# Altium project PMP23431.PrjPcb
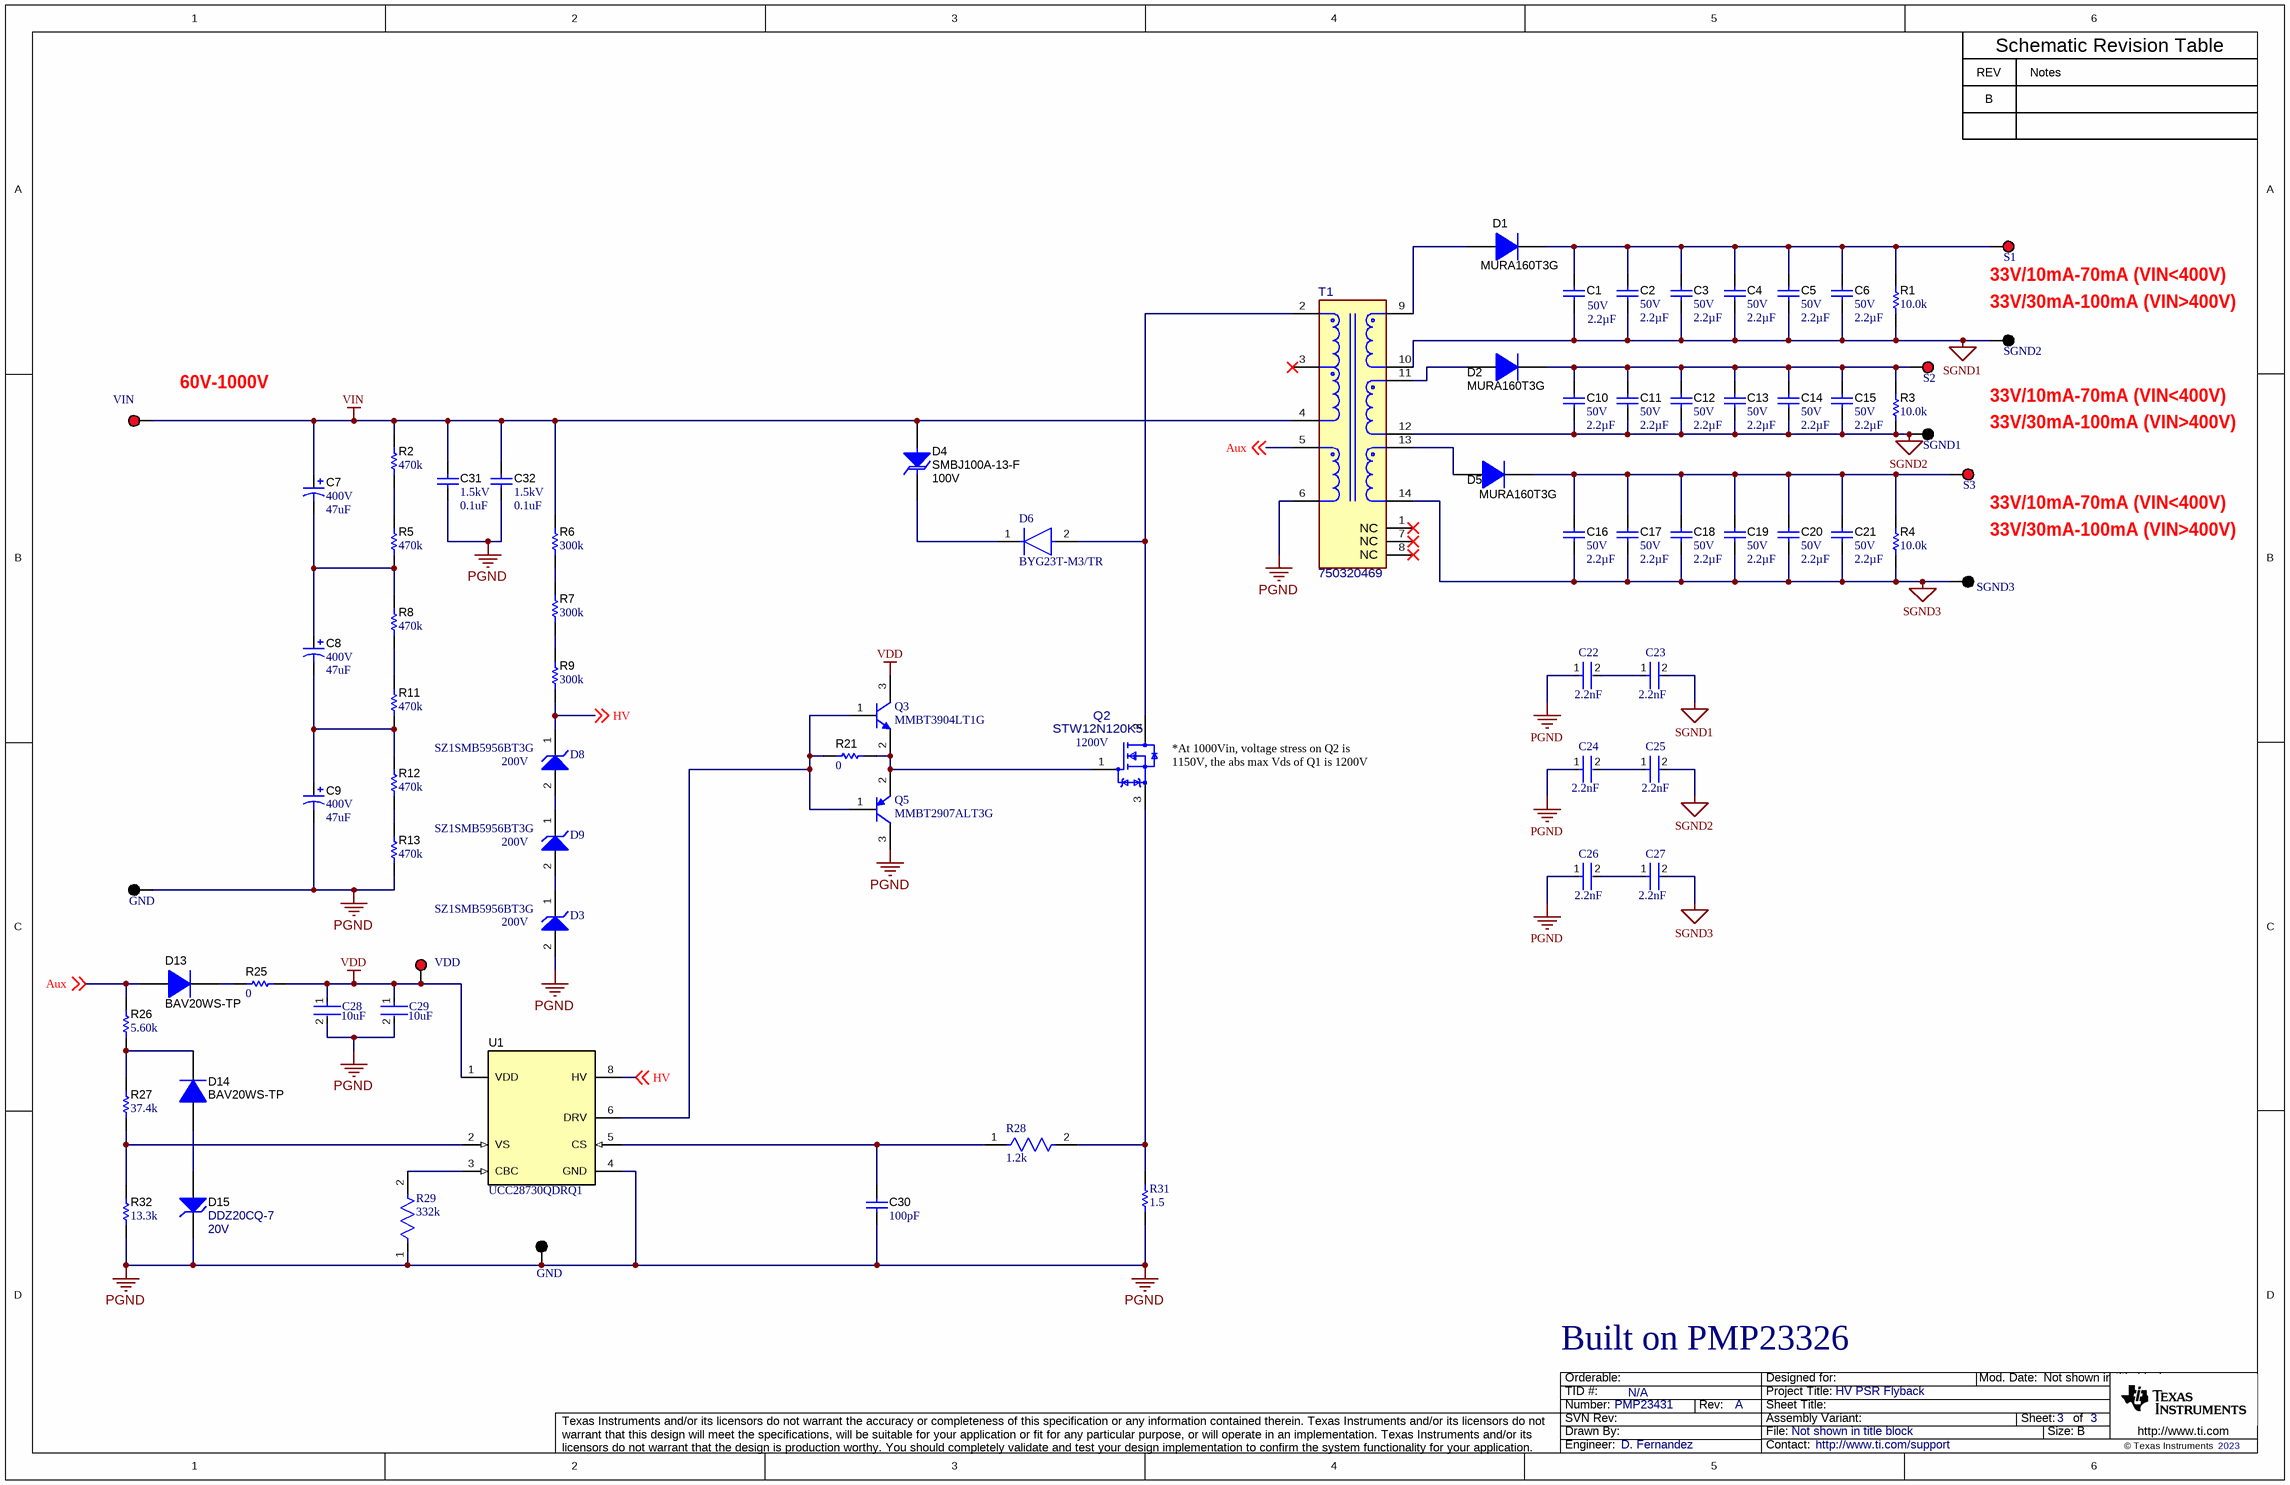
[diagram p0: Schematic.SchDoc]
CopyrightYear: 2023; PCB_Rev: A; PRJ_Engineer: D. Fernandez; PRJ_Number: PMP23431; PRJ_Title: HV PSR Flyback; SCH_Rev: A; TechSupport: http://www.ti.com/support; TID: N/A
1 sheet, 78 parts. Net scope: global (net labels, ports and power ports of the same name join across sheets).
Board file: Pcb.PcbDoc

## Sheet Schematic.SchDoc
size 431 x 279 mm; Date: Not shown in title block; ApprovedBy: Not shown in title block; CheckedBy: Not shown in title block; Author: Not shown in title block; CompanyName: Not shown in title block; Engineer: Not shown in title block; Organization: Not shown in title block; Address1: Not shown in title block; Address2: Not shown in title block; Address3: Not shown in title block; Address4: Not shown in title block; DocumentNumber: 3; Revision: Use project parameter SCH_Rev; SheetNumber: 3; SheetTotal: 3; PageSetup: Record=PageOptions¦CenterHorizontal=True¦CenterVertical=True¦PrintScale=1.00¦XCorrection=1.00¦YCorrection=1.00¦PrintKind=0¦BorderSize=5000000¦LeftOffset=0¦BottomOffset=0¦Orientation=2¦PaperLength=1000¦PaperWidth=1000¦Scale=100¦PaperSource=15¦PrintQuality=600¦MediaType=1¦DitherType=10¦PaperKind=Letter¦PrintScaleMode=1

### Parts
(Parts that share a designator on the sheet are numbered #1, #2 ... from top to bottom, then left to right.)
C1  VDC_V: 50V  ValueDisplayed: 2.2µF  [1206_180]  (hidden comment: UMJ316AB7225KLHT)
C2  VDC_V: 50V  ValueDisplayed: 2.2µF  [1206_180]  (hidden comment: UMJ316AB7225KLHT)
C3  VDC_V: 50V  ValueDisplayed: 2.2µF  [1206_180]  (hidden comment: UMJ316AB7225KLHT)
C4  VDC_V: 50V  ValueDisplayed: 2.2µF  [1206_180]  (hidden comment: UMJ316AB7225KLHT)
C5  VDC_V: 50V  ValueDisplayed: 2.2µF  [1206_180]  (hidden comment: UMJ316AB7225KLHT)
C6  VDC_V: 50V  ValueDisplayed: 2.2µF  [1206_180]  (hidden comment: UMJ316AB7225KLHT)
C7  VDC_V: 400V  ValueDisplayed: 47uF  [EE_1800x2000]  (hidden comment: EEU-EE2G470S)
C8  VDC_V: 400V  ValueDisplayed: 47uF  [EE_1800x2000]  (hidden comment: EEU-EE2G470S)
C9  VDC_V: 400V  ValueDisplayed: 47uF  [EE_1800x2000]  (hidden comment: EEU-EE2G470S)
C10  VDC_V: 50V  ValueDisplayed: 2.2µF  [1206_180]  (hidden comment: UMJ316AB7225KLHT)
C11  VDC_V: 50V  ValueDisplayed: 2.2µF  [1206_180]  (hidden comment: UMJ316AB7225KLHT)
C12  VDC_V: 50V  ValueDisplayed: 2.2µF  [1206_180]  (hidden comment: UMJ316AB7225KLHT)
C13  VDC_V: 50V  ValueDisplayed: 2.2µF  [1206_180]  (hidden comment: UMJ316AB7225KLHT)
C14  VDC_V: 50V  ValueDisplayed: 2.2µF  [1206_180]  (hidden comment: UMJ316AB7225KLHT)
C15  VDC_V: 50V  ValueDisplayed: 2.2µF  [1206_180]  (hidden comment: UMJ316AB7225KLHT)
C16  VDC_V: 50V  ValueDisplayed: 2.2µF  [1206_180]  (hidden comment: UMJ316AB7225KLHT)
C17  VDC_V: 50V  ValueDisplayed: 2.2µF  [1206_180]  (hidden comment: UMJ316AB7225KLHT)
C18  VDC_V: 50V  ValueDisplayed: 2.2µF  [1206_180]  (hidden comment: UMJ316AB7225KLHT)
C19  VDC_V: 50V  ValueDisplayed: 2.2µF  [1206_180]  (hidden comment: UMJ316AB7225KLHT)
C20  VDC_V: 50V  ValueDisplayed: 2.2µF  [1206_180]  (hidden comment: UMJ316AB7225KLHT)
C21  VDC_V: 50V  ValueDisplayed: 2.2µF  [1206_180]  (hidden comment: UMJ316AB7225KLHT)
C22  Capacitance: 2.2nF  [FP-C4532-130-MFG]  (hidden comment: C4532X7R3D222K130KA)
C23  Capacitance: 2.2nF  [FP-C4532-130-MFG]  (hidden comment: C4532X7R3D222K130KA)
C24  Capacitance: 2.2nF  [FP-C4532-130-MFG]  (hidden comment: C4532X7R3D222K130KA)
C25  Capacitance: 2.2nF  [FP-C4532-130-MFG]  (hidden comment: C4532X7R3D222K130KA)
C26  Capacitance: 2.2nF  [FP-C4532-130-MFG]  (hidden comment: C4532X7R3D222K130KA)
C27  Capacitance: 2.2nF  [FP-C4532-130-MFG]  (hidden comment: C4532X7R3D222K130KA)
C28  Capacitance: 10uF  [FP-CGA5L-0_3-0_1-MFG]
C29  Capacitance: 10uF  [FP-CGA5L-0_3-0_1-MFG]
C30  ValueDisplayed: 100pF  [0603]  (hidden comment: CGA3E2NP01H101J080AA)
C31  VDC_V: 1.5kV  ValueDisplayed: 0.1uF  [2225]  (hidden comment: C2225C104KFRACTU)
C32  VDC_V: 1.5kV  ValueDisplayed: 0.1uF  [2225]  (hidden comment: C2225C104KFRACTU)
D1  MURA160T3G  [SMA]
D2  MURA160T3G  [SMA]
D3  SZ1SMB5956BT3G  VZ Typ (V): 200V  [ONSC-SMB-2-403A-03_H_V]
D4  SMBJ100A-13-F  value 100V  [SMB]
D5  MURA160T3G  [SMA]
D6  BYG23T-M3/TR  [FP-SMA-MFG]
D8  SZ1SMB5956BT3G  VZ Typ (V): 200V  [ONSC-SMB-2-403A-03_H_V]
D9  SZ1SMB5956BT3G  VZ Typ (V): 200V  [ONSC-SMB-2-403A-03_H_V]
D13  BAV20WS-TP  [SOD-323]
D14  BAV20WS-TP  [SOD-323]
D15  DDZ20CQ-7  value 20V  [SOD-123]
GND#1  5011  [Keystone5011]  (value not drawn)
GND#2  5011  [Keystone5011]  (value not drawn)
Q2  STW12N120K5  Drain To Source Breakdown Voltage: 1200V  [FP-STW12N120K5_TO-247-3-MFG]
Q3  MMBT3904LT1G  [ONSC-SOT-23-3-318-08_V]
Q5  MMBT2907ALT3G  [ONSC-SOT-23-3-318-08_V]
R1  ValueDisplayed: 10.0k  [1206]  (hidden comment: ERJ-8ENF1002V)
R2  ValueDisplayed: 470k  [1206]  (hidden comment: CRCW1206470KJNEA)
R3  ValueDisplayed: 10.0k  [1206]  (hidden comment: ERJ-8ENF1002V)
R4  ValueDisplayed: 10.0k  [1206]  (hidden comment: ERJ-8ENF1002V)
R5  ValueDisplayed: 470k  [1206]  (hidden comment: CRCW1206470KJNEA)
R6  ValueDisplayed: 300k  [1206]  (hidden comment: CRCW1206300KJNEA)
R7  ValueDisplayed: 300k  [1206]  (hidden comment: CRCW1206300KJNEA)
R8  ValueDisplayed: 470k  [1206]  (hidden comment: CRCW1206470KJNEA)
R9  ValueDisplayed: 300k  [1206]  (hidden comment: CRCW1206300KJNEA)
R11  ValueDisplayed: 470k  [1206]  (hidden comment: CRCW1206470KJNEA)
R12  ValueDisplayed: 470k  [1206]  (hidden comment: CRCW1206470KJNEA)
R13  ValueDisplayed: 470k  [1206]  (hidden comment: CRCW1206470KJNEA)
R21  ValueDisplayed: 0  [0603]  (hidden comment: RMCF0603ZT0R00)
R25  ValueDisplayed: 0  [0603]  (hidden comment: RMCF0603ZT0R00)
R26  ValueDisplayed: 5.60k  [0603]  (hidden comment: ERJ3EKF5601V)
R27  ValueDisplayed: 37.4k  [0603]  (hidden comment: ERA-3AEB3742V)
R28  1.2k  [FP-ERA3A-IPC_C]
R29  332k  [FP-RG1608-MFG]
R31  1.5  [RESC3216X70X50NL05T20]
R32  ValueDisplayed: 13.3k  [0603]  (hidden comment: CRCW060313K3FKEA)
S1  5010  [Keystone5010]  (value not drawn)
S2  5010  [Keystone5010]  (value not drawn)
S3  5010  [Keystone5010]  (value not drawn)
SGND1  5011  [Keystone5011]  (value not drawn)
SGND2  5011  [Keystone5011]  (value not drawn)
SGND3  5011  [Keystone5011]  (value not drawn)
T1  750320469  [FP-750320469_PTH14-MFG]
U1  UCC28730QDRQ1  [D0007A_N]
VDD  5010  [Keystone5010]  (value not drawn)
VIN  5010  [Keystone5010]  (value not drawn)

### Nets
PGND: C9.2(-) C22.1 C24.1 C26.1 C28.2 C29.2 C30.2 C31.2 C32.2 D3.2(A) D15.1(K) GND#1.1 GND#2.1 Q5.3(C) R13.1 R29.1 R31.1 R32.1 T1.6 U1.4(GND)
SGND1: C1.2 C2.2 C3.2 C4.2 C5.2 C6.2 C23.2 R1.1 SGND2.1 T1.10
SGND2: C10.2 C11.2 C12.2 C13.2 C14.2 C15.2 C25.2 R3.1 SGND1.1 T1.12
SGND3: C16.2 C17.2 C18.2 C19.2 C20.2 C21.2 C27.2 R4.1 SGND3.1 T1.14
VDD: C28.1 C29.1 Q3.3(C) R25.2 U1.1(VDD) VDD.1
VIN: C7.1(+) C31.1 C32.1 D4.2(A) R2.2 R6.2 T1.4 VIN.1
Aux: D13.2(A) R26.2 T1.5 ; off-sheet Aux
HV: D8.1(K) R9.1 U1.8(HV) ; off-sheet HV
NetC1_1: C1.1 C2.1 C3.1 C4.1 C5.1 C6.1 D1.1(K) R1.2 S1.1
NetC7_2: C7.2(-) C8.1(+) R5.1 R8.2
NetC8_2: C8.2(-) C9.1(+) R11.1 R12.2
NetC10_1: C10.1 C11.1 C12.1 C13.1 C14.1 C15.1 D2.1(K) R3.2 S2.1
NetC16_1: C16.1 C17.1 C18.1 C19.1 C20.1 C21.1 D5.1(K) R4.2 S3.1
NetC22_2: C22.2 C23.1
NetC24_2: C24.2 C25.1
NetC26_2: C26.2 C27.1
NetC30_1: C30.1 R28.1 U1.5(CS)
NetD1_2: D1.2(A) T1.9
NetD2_2: D2.2(A) T1.11
NetD3_1: D3.1(K) D9.2(A)
NetD4_1: D4.1(K) D6.1(C)
NetD5_2: D5.2(A) T1.13
NetD6_2: D6.2(A) Q2.2(D) T1.2
NetD8_2: D8.2(A) D9.1(K)
NetD13_1: D13.1(K) R25.1
NetD14_1: D14.1(K) R26.1 R27.2
NetD14_2: D14.2(A) D15.2(A)
NetQ2_1: Q2.1(G) Q3.2(E) Q5.2(E) R21.2
NetQ2_3: Q2.3(S) R28.2 R31.2
NetQ3_1: Q3.1(B) Q5.1(B) R21.1 U1.6(DRV)
NetR2_1: R2.1 R5.2
NetR6_1: R6.1 R7.2
NetR7_1: R7.1 R9.2
NetR8_1: R8.1 R11.2
NetR12_1: R12.1 R13.2
NetR27_1: R27.1 R32.2 U1.2(VS)
NetR29_2: R29.2 U1.3(CBC)

Not connected (* = marked no-connect by the designer): T1 1(NC)* 3* 7(NC)* 8(NC)*

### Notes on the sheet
- REV
- B
- Notes
- Schematic Revision Table
- (near S1) 33V/10mA-70mA (VIN<400V)
- (near SGND2) 33V/30mA-100mA (VIN>400V)
- (near VIN) 60V-1000V
- 33V/10mA-70mA (VIN<400V)
- 33V/30mA-100mA (VIN>400V)
- (near S3) 33V/10mA-70mA (VIN<400V)
- (near Q2) *At 1000Vin, voltage stress on Q2 is 1150V, the abs max Vds of Q1 is 1200V
- Built on PMP23326

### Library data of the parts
C1-C6 C10-C21 = CMP-0080745-1: CAP, CERM, 2.2 µF, 50 V,+/- 10%, X7R, AEC-Q200 Grade 1, 1206; Manufacturer: Taiyo Yuden; SizeAreaWB_mm2: 10.92; SizeArea_mm2: 5.12; AEC Qualified: Y; AEC Category: Q200; Value: 2.2uF; TaMax_C: 125°C; SizeZ_mm: 1.8; AEC Grade: 1; Polarized: N; TaMin_C: -55°C; SizeY_mm: 1.6; U/M: EA; SizeX_mm: 3.2; Cap_Case: 1206
C7-C9 = CMP-0010026-1: CAP, AL, 47 uF, 400 V, +/- 20%, TH; Manufacturer: Panasonic; TaMin_C: -25°C; Polarized: Y; SizeAreaWB_mm2: 400; Value1: Unknown; U/M: EA; Value: 47uF; TaMax_C: 105°C; SizeZ_mm: 22; SizeX_mm: 18; Cap_Case: 18x20; SizeArea_mm2: 324; CompType: Capacitor; AEC Qualified: N; Cap_F: 47µF; IRMS_A: 1.18A; AEC Category: Q200
C22-C27 = CMP-08246-007253-1: CAP CER 2200PF 2KV X7R 1812; Tolerance: 10%
C28 C29 = CMP-08246-001891-1: Cap Ceramic 10uF 50V X7R 10% Pad SMD 1206 +125°C Automotive T/R
C30 = CMP-0007075-4: CAP, CERM, 100 pF, 50 V, +/- 5%, C0G/NP0, AEC-Q200 Grade 0, 0603; Manufacturer: TDK; TaMin_C: -55°C; Polarized: N; SizeAreaWB_mm2: 4.68; Value1: Unknown; U/M: EA; Value: 100pF; TaMax_C: 150°C; SizeZ_mm: 1; SizeX_mm: 1.6; SizeY_mm: 0.8; Value2: 50V; SizeArea_mm2: 1.28; AEC Qualified: Y; AEC Grade: 0; AEC Category: Q200
C31 C32 = CMP-0009331-2: CAP, CERM, 0.1 uF, 1500 V, +/- 10%, X7R, 2225; Manufacturer: Kemet; TaMin_C: -55°C; Polarized: N; SizeAreaWB_mm2: 63.91; Value1: Unknown; U/M: EA; Value: 0.1uF; TaMax_C: 125°C; SizeZ_mm: 2; SizeX_mm: 5.7; SizeY_mm: 6.3; Value2: 1500V; SizeArea_mm2: 35.91; Cap_F: 100nF; AEC Category: Q200
D1 D2 D5 = CMP-0029033-2: Diode, Ultrafast, 600 V, 1 A, AEC-Q101, SMA; Manufacturer: ON Semiconductor; AEC Category: Q101; SizeX_mm: 5.59; Io_A: 1A; Green_Lifecycle: Active; Value2: 1.05V; SizeArea_mm2: 16.3228; SizeZ_mm: 2.87; TJmax_C: 175°C; Value: 600V; AEC Qualified: Y; SizeAreaWB_mm2: 37.3428; SizeY_mm: 2.92; Green_REACh: Passed
D3 D8 D9 = CMP-1060-00171-1: 3 W Zener Voltage Regulator, 2-Pin SMB, Pb-Free, Tape and Reel; Manufacturer: On Semiconductor
D4 = CMP-0005571-3: Diode, TVS, Uni, 100 V, 162 Vc, SMB; Manufacturer: Diodes Inc.; SizeAreaWB_mm2: 44.156; SizeArea_mm2: 21.336; Vbr_Min: 111V; Value1: 600W; AEC Category: Q101; Ipp: 3.7A; Vbr_Max: 128V; SizeY_mm: 3.81; SizeZ_mm: 2.6; Vc: 162V; SizeX_mm: 5.6
D6 = CMP-02540-000071-1: DIODE AVALANCHE 1300V 1A DO214AC; Element Configuration: Single; Reverse Voltage: 1.3kV; Zener Voltage: 200V; Reverse Recovery Time: 75ns; Max Forward Surge Current (Ifsm): 18A; Max Reverse Current: 5uA; Max Power Dissipation: 800mW; Forward Voltage: 1.74V
D13 D14 = CMP-0029044-2: Diode, P-N, 150 V, 0.2 A, SOD-323; Manufacturer: Micro Commercial Components; Value2: 1.25V; AEC Category: Q101; SizeArea_mm2: 3.645; Vr_V: 150V; Green_REACh: Incomplete; SizeZ_mm: 1; Green_Lifecycle: Not Set; TJmax_C: 150°C; SizeAreaWB_mm2: 8.695; Value1: 0.2A; SizeX_mm: 2.7; Io_A: 200mA; SizeY_mm: 1.35; Value: 150V
D15 = CMP-0085147-1: Diode, Zener, 20 V, 500 mW, AEC-Q101, SOD-123; Manufacturer: Diodes Inc.; SizeX_mm: 3.85; AEC Category: Q101; SizeAreaWB_mm2: 13.095; SizeArea_mm2: 6.545; RJA_CperW: 425; SizeY_mm: 1.7; AEC Qualified: Y; SizeZ_mm: 1.35; Value1: 0.5W; Power_W: 500mW
GND#1 GND#2 SGND1-SGND3 = CMP-0055148-1: Test Point, Multipurpose, Black, TH; Manufacturer: Keystone; CNHeader: FALSE; Green_Lifecycle: Active; Green_REACh: Passed; ContactFinish: Silver; CT: TRUE
Q2 = CMP-0036771-1: N-Channel 1200 V 12A (Tc) 250W (Tc) Through Hole TO-247-3; Manufacturer: STMicroelectronics; AEC Qualified: No; QgTyp_nC: 44.2nC @ 10V; Rdson45_ohm: 0.62; SizeZ_mm: 24.45mm; VdsMax_V: 1.5V; Vgs_V: 30V; ChMode: False; Input Capacitace At Vds: 1370pF @ 100V; Number Of Channels: 1; Pulse Drain Current: 48A; Reverse Recovery Charge: 12600nC; Reverse Recovery Time: 630ns; Rthja Max: 50°C/W; Standoff Height: 3.7mm; Threshold Vgs Max: 5V; Threshold Vgs Min: 3V; TJmax_C: +150°C; Turn Off Delay Time: 68.5ns; Turn On Delay Time: 23ns
Q3 = CMP-1048-00631-1: General Purpose Transistor, NPN Silicon, 3-Pin SOT-23, Pb-Free, Tape and Reel; Manufacturer: On Semiconductor; IC Continuous (A): 0.2; fT Min (MHz): 300
Q5 = CMP-1048-00587-1: General Purpose Transistor, PNP Silicon, 3-Pin SOT-23, Pb-Free, Tape and Reel; Manufacturer: On Semiconductor; IC Continuous (A): -0.6; fT Min (MHz): 200
R1 R3 R4 = CMP-0017284-3: RES, 10.0 k, 1%, 0.25 W, AEC-Q200 Grade 0, 1206; Manufacturer: Panasonic; Power_W: 250mW; TempCo: 100 ppm/C; Value_Code: 10k0; Value: 10.0k; EIA_Code: E96; Res_ohm: 10k; SizeX_mm: 3.2; SizeY_mm: 1.6; SizeZ_mm: 1.35; Value2: 0.25W; SizeArea_mm2: 5.12; AEC Qualified: Y; VDC_V: 200V; AEC Category: Q200; AEC Grade: 0; SizeAreaWB_mm2: 10.92
R2 R5 R8 R11-R13 = CMP-0018684-3: RES, 470 k, 5%, 0.25 W, AEC-Q200 Grade 0, 1206; Manufacturer: Vishay-Dale; Power_W: 250mW; TempCo: 200 ppm/C; Value: 470k; EIA_Code: E24; SizeX_mm: 3.2; SizeY_mm: 1.6; SizeZ_mm: 1.35; Value2: 0.25W; SizeArea_mm2: 5.12; AEC Qualified: Y; VDC_V: 200V; AEC Category: Q200; AEC Grade: 0
R6 R7 R9 = CMP-0018652-3: RES, 300 k, 5%, 0.25 W, AEC-Q200 Grade 0, 1206; Manufacturer: Vishay-Dale; Power_W: 250mW; TempCo: 200 ppm/C; Value: 300k; EIA_Code: E24; SizeX_mm: 3.2; SizeY_mm: 1.6; SizeZ_mm: 1.35; Value2: 0.25W; SizeArea_mm2: 5.12; AEC Qualified: Y; VDC_V: 200V; AEC Category: Q200; AEC Grade: 0
R21 R25 = CMP-0023343-3: RES, 0, 1%, 0.1 W, AEC-Q200 Grade 0, 0603; Manufacturer: Stackpole Electronics Inc; Power_W: 100mW; TempCo: ppm/C; U/M: EA; Value: 0; SizeX_mm: 1.6; SizeY_mm: 0.8; SizeZ_mm: 1; Value2: 0.1W; SizeArea_mm2: 1.28; AEC Qualified: Y; AEC Category: Q200
R26 = CMP-0078666-1: RES, 5.60 k, 1%, 0.1 W, AEC-Q200 Grade 0, 0603; Manufacturer: Panasonic; Power_W: 100mW; TempCo: 100 ppm/C; Value_Code: 5k60; Value: 5.60k; Res_ohm: 5.6k; SizeX_mm: 1.6; SizeY_mm: 0.8; SizeZ_mm: 1; Value2: 0.1W; SizeArea_mm2: 1.28; AEC Qualified: Y; AEC Grade: 0; AEC Category: Q200
R27 = CMP-0860903-1: RES, 37.4 k, 0.1%, 0.1 W, AEC-Q200 Grade 0, 0603; Manufacturer: Panasonic; Value2: 0.1W; Value: 37.4k; AEC Grade: 0; Power_W: 100mW; AEC Category: Q200; TempCo: 25 ppm/C; SizeZ_mm: 1; SizeAreaWB_mm2: 4.68; AEC Qualified: Y; SizeY_mm: 0.8; EIA_Code: E192; VDC_V: 75V; Value_Code: 37k4; SizeArea_mm2: 1.28; SizeX_mm: 1.6
R28 = CMP-2000-00897-2: RES SMD 1.2K OHM 0.1% 1/10W 0603; Resistance: 1.2kR; Power Rating: 100mW; Temperature Coefficient: 25ppm/°C; Voltage Rating: 75V
R29 = CMP-2000-02200-2: Automotive Metal Thin Film Chip Resistor, 0603, 332kΩ, 0.1%, 25ppm/°C, 0.1W, 100V; Power Rating: 62.5mW; Max Power Dissipation: 100mW; Resistance: 332kR; Voltage Rating (DC): 75V
R31 = CMP-2003-00683-1: Manufacturer: Panasonic; Part Number: ERJ-8RQF1R5V
R32 = CMP-0022043-4: RES, 13.3 k, 1%, 0.1 W, AEC-Q200 Grade 0, 0603; Manufacturer: Vishay-Dale; Power_W: 100mW; TempCo: 100 ppm/C; Value_Code: 13k3; Value: 13.3k; EIA_Code: E96; SizeX_mm: 1.6; SizeY_mm: 0.8; SizeZ_mm: 1; Value2: 0.1W; SizeArea_mm2: 1.28; AEC Qualified: Y; VDC_V: 75V; AEC Category: Q200; AEC Grade: 0
S1-S3 VDD VIN = CMP-0055147-1: Test Point, Multipurpose, Red, TH; Manufacturer: Keystone; CNHeader: FALSE; Green_Lifecycle: Active; Green_REACh: Passed; ContactFinish: Silver; CT: TRUE
T1 = CMP-0120025-1: TRANSFORMER; Manufacturer: Wurth Electronics; DCR_ohm: 3.19; Ind_H: 1mH; Ns1toNp: 2.74:1; Rsec1_ohm: 1.82; SizeZ_mm: 25.2mm; AEC Qualified: No; Frequency_Fixed: 75kHz; Voltage_Isolation_Vrms: 6.9kV
U1 = CMP-0065056-3: Zero Standby PSR Flyback Controller with CVCC and Wake-Up Monitoring, Automotive, D0007A (SOIC-7); Manufacturer: Texas Instruments; SizeX_mm: 6.0; SizeY_mm: 4.9; CompType: IC; SizeZ_mm: 1.75; SizeArea_mm2: 29.4; SizeAreaWB_mm2: 55.2; U/M: EA; AEC Category: Q200; AEC Qualified: N

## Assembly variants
001: not fitted C30 R1 R3 R4 R21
